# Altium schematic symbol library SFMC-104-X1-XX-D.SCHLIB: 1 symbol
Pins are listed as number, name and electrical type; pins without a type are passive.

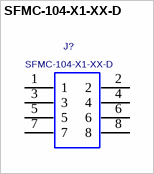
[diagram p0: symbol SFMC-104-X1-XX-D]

## SFMC-104-X1-XX-D
designator J?
Socket Strip, Cuttable, Double Row, 0.050"x0.050" Pitch; MANUFACTURER: SAMTEC
footprint SFMC-104-X1-XX-D
pins: 1, 2, 3, 4, 5, 6, 7, 8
